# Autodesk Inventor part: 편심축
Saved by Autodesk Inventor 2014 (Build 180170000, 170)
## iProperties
Created: 2024-08
Part Number: 편심축
Material: 일반
Document SubType Name: Modeling
Designer: dg
Density: 1 g/cm^3
Appearance: 기본값
Author: dg
Author: jhkim
Creation Date: 2024-08-09
Sending System: Autodesk Inventor 2025
Preprocessor: ST-DEVELOPER v20
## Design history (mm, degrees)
node "편심축1"
node "솔리드1"
node "기준1"
